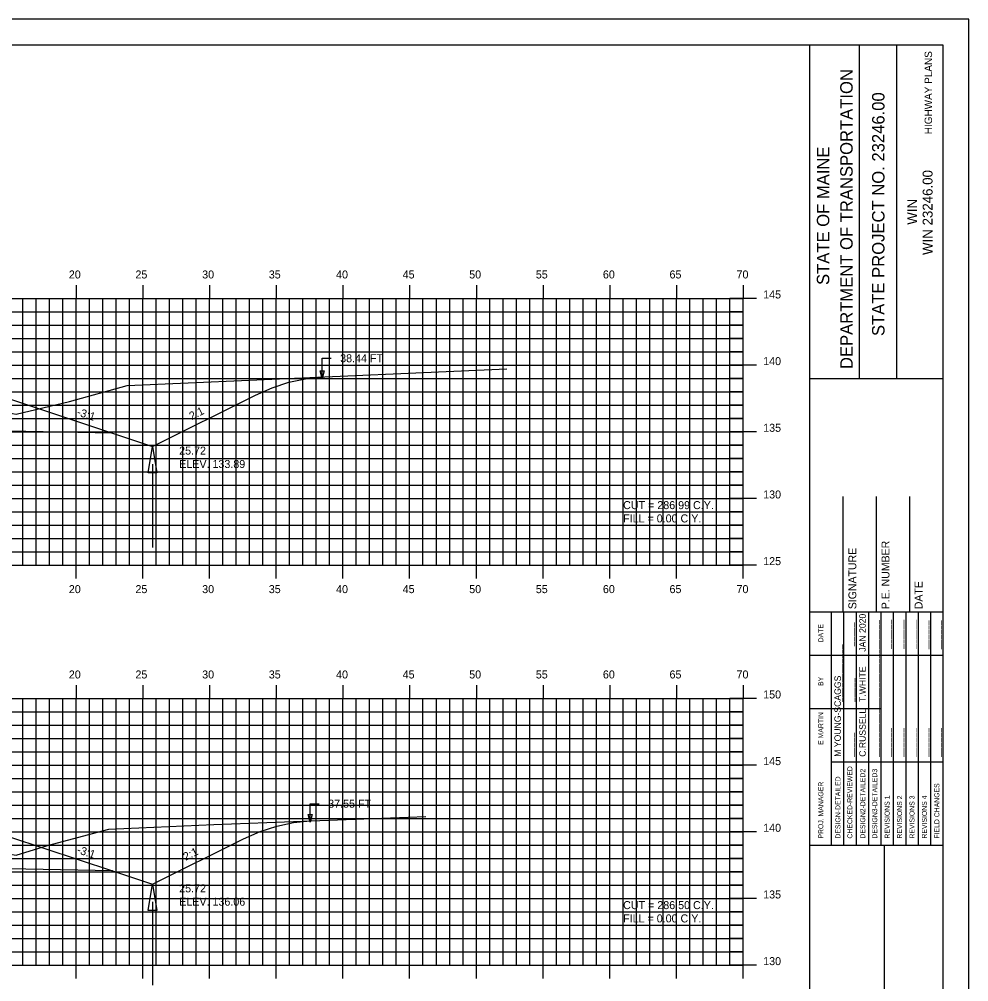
# Model space of a CAD drawing. Extents: x 1145194 to 1145364, y 608981 to 609091.
# Drawn here: x 1145292.9 to 1145364, y 609019.1 to 609091.3 of the extents above; entities that cross this region are included whole.
import ezdxf

# ---------------------------------------------------------------- set-up
doc = ezdxf.new("R2010")
doc.units = 0
for name, color, linetype in [('ANNOTATION', 7, 'Continuous'), ('BORDER', 7, 'Continuous'), ('D_Drainage_Ditch_Line', 7, 'Continuous'), ('D_Roadway_SlopeLines', 7, 'Continuous'), ('D_Roadway_SubGrade', 7, 'Continuous'), ('D_Text_Standard', 7, 'Continuous'), ('H_V ANNOTATION', 7, 'Continuous'), ('HIGHWAY_TITLE', 7, 'Continuous'), ('MAJOR', 7, 'Continuous'), ('MINOR', 7, 'Continuous'), ('PLOT BOUNDARY', 7, 'Continuous'), ('S_Roadway_Centerline', 7, 'Continuous')]:
    doc.layers.add(name, color=color, linetype=linetype)

msp = doc.modelspace()

# ---------------------------------------------------------------- linework, layer by layer
for points in [[(1145240.362, 609063.649), (1145241.612, 609063.504), (1145242.862, 609063.221), (1145244.112, 609062.802), (1145245.362, 609062.245), (1145251.407, 609059.223), (1145254.407, 609060.223), (1145262.131, 609062.797), (1145262.132, 609062.797), (1145266.132, 609062.957), (1145277.132, 609063.177), (1145288.132, 609062.957), (1145292.132, 609062.797), (1145299.855, 609060.223), (1145302.855, 609059.223), (1145310.577, 609063.083), (1145311.827, 609063.637), (1145313.077, 609064.048), (1145314.327, 609064.317), (1145315.577, 609064.443)], [(1145240.436, 609030.623), (1145241.686, 609030.548), (1145242.936, 609030.316), (1145244.186, 609029.927), (1145245.436, 609029.38), (1145251.407, 609026.395), (1145254.407, 609027.395), (1145262.131, 609029.969), (1145262.132, 609029.969), (1145266.132, 609030.129), (1145277.132, 609030.349), (1145288.132, 609030.129), (1145292.132, 609029.969), (1145299.855, 609027.395), (1145302.855, 609026.395), (1145309.682, 609029.808), (1145310.932, 609030.361), (1145312.182, 609030.769), (1145313.432, 609031.033), (1145314.682, 609031.153)]]:
    msp.add_lwpolyline(points)
at = {"layer": 'BORDER'}
for p, q in [((1145352.132, 608984.335), (1145352.132, 609089.335)), ((1145355.861, 609064.332), (1145355.861, 609089.332)), ((1145358.656, 609064.332), (1145358.656, 609089.332)), ((1145352.133, 609064.329), (1145362.132, 609064.329)), ((1145354.632, 609046.838), (1145354.632, 609055.485)), ((1145357.132, 609046.838), (1145357.132, 609055.485)), ((1145359.632, 609046.838), (1145359.632, 609055.485)), ((1145352.132, 609046.838), (1145362.132, 609046.838)), ((1145352.132, 609029.338), (1145362.132, 609029.338)), ((1145357.723, 608994.338), (1145357.723, 609029.338))]:
    msp.add_line(p, q, dxfattribs=at)
msp.add_lwpolyline([(1145202.132, 608984.335), (1145362.132, 608984.335), (1145362.132, 609089.335), (1145202.132, 609089.335)], close=True, dxfattribs=at)
for points in [[(1145353.747, 609043.588), (1145353.747, 609046.838)], [(1145354.68, 609029.341), (1145354.68, 609046.838)], [(1145355.611, 609046.838), (1145355.611, 609029.341)], [(1145356.543, 609029.341), (1145356.543, 609046.838)], [(1145357.475, 609029.341), (1145357.475, 609046.838)], [(1145358.406, 609029.341), (1145358.406, 609046.838)], [(1145359.338, 609029.341), (1145359.338, 609046.838)], [(1145360.27, 609029.341), (1145360.27, 609046.838)], [(1145361.201, 609029.341), (1145361.201, 609046.838)], [(1145353.748, 609029.341), (1145353.748, 609046.132)], [(1145352.132, 609043.588), (1145362.132, 609043.588)], [(1145352.132, 609039.588), (1145353.748, 609039.588)], [(1145353.747, 609039.588), (1145357.474, 609039.588)], [(1145353.747, 609035.588), (1145362.132, 609035.588)]]:
    msp.add_lwpolyline(points, dxfattribs=at)
at = {"layer": 'D_Drainage_Ditch_Line'}
for p, q in [((1145302.856, 609057.91), (1145302.855, 609051.667)), ((1145302.856, 609025.082), (1145302.855, 609018.839))]:
    msp.add_line(p, q, dxfattribs=at)
for points in [[(1145303.184, 609057.254), (1145302.527, 609057.254), (1145302.855, 609059.223)], [(1145303.184, 609024.426), (1145302.527, 609024.426), (1145302.855, 609026.395)]]:
    msp.add_lwpolyline(points, close=True, dxfattribs=at)
at = {"layer": 'D_Roadway_SlopeLines'}
for points in [[(1145302.855, 609059.223), (1145310.577, 609063.083), (1145311.827, 609063.637), (1145313.077, 609064.048), (1145314.327, 609064.317), (1145315.577, 609064.443)], [(1145299.855, 609060.223), (1145302.855, 609059.223)], [(1145302.855, 609026.395), (1145309.682, 609029.808), (1145310.932, 609030.361), (1145312.182, 609030.769), (1145313.432, 609031.033), (1145314.682, 609031.153)], [(1145299.855, 609027.395), (1145302.855, 609026.395)]]:
    msp.add_lwpolyline(points, dxfattribs=at)
at = {"layer": 'D_Roadway_SubGrade'}
for points in [[(1145288.132, 609062.54), (1145288.132, 609062.707), (1145292.132, 609062.547), (1145292.132, 609062.797), (1145292.132, 609062.797), (1145299.855, 609060.223), (1145288.132, 609060.457)], [(1145288.132, 609029.712), (1145288.132, 609029.879), (1145292.132, 609029.719), (1145292.132, 609029.969), (1145292.132, 609029.969), (1145299.855, 609027.395), (1145288.132, 609027.629)]]:
    msp.add_lwpolyline(points, close=True, dxfattribs=at)
at = {"layer": 'D_Text_Standard'}
for points in [[(1145315.577, 609064.333), (1145315.564, 609065.851), (1145316.244, 609065.851)], [(1145314.682, 609031.058), (1145314.669, 609032.443), (1145315.349, 609032.443)]]:
    msp.add_lwpolyline(points, dxfattribs=at)
for points in [[(1145315.577, 609064.333), (1145315.426, 609064.914), (1145315.718, 609064.917)], [(1145314.682, 609031.058), (1145314.531, 609031.639), (1145314.822, 609031.641)]]:
    msp.add_lwpolyline(points, close=True, dxfattribs=at)
at = {"layer": 'MAJOR'}
for p, q in [((1145297.132, 609071.337), (1145297.132, 609070.335)), ((1145302.132, 609071.337), (1145302.132, 609070.335)), ((1145307.132, 609071.337), (1145307.132, 609070.335)), ((1145312.132, 609071.337), (1145312.132, 609070.335)), ((1145317.132, 609071.337), (1145317.132, 609070.335)), ((1145322.132, 609071.337), (1145322.132, 609070.335)), ((1145327.132, 609071.337), (1145327.132, 609070.335)), ((1145332.132, 609071.337), (1145332.132, 609070.335)), ((1145337.132, 609071.337), (1145337.132, 609070.335)), ((1145342.132, 609071.337), (1145342.132, 609070.335)), ((1145347.132, 609071.337), (1145347.132, 609070.335)), ((1145207.132, 609070.335), (1145347.132, 609070.335)), ((1145207.132, 609070.335), (1145347.132, 609070.335)), ((1145297.132, 609050.335), (1145297.132, 609070.335)), ((1145302.132, 609050.335), (1145302.132, 609070.335)), ((1145307.132, 609050.335), (1145307.132, 609070.335)), ((1145312.132, 609050.335), (1145312.132, 609070.335)), ((1145317.132, 609050.335), (1145317.132, 609070.335)), ((1145322.132, 609050.335), (1145322.132, 609070.335)), ((1145327.132, 609050.335), (1145327.132, 609070.335)), ((1145332.132, 609050.335), (1145332.132, 609070.335)), ((1145337.132, 609050.335), (1145337.132, 609070.335)), ((1145342.132, 609050.335), (1145342.132, 609070.335)), ((1145348.134, 609070.335), (1145346.13, 609070.335)), ((1145347.132, 609050.335), (1145347.132, 609070.335)), ((1145347.132, 609050.335), (1145347.132, 609070.335)), ((1145207.132, 609065.335), (1145347.132, 609065.335)), ((1145348.134, 609065.335), (1145346.13, 609065.335)), ((1145207.132, 609060.335), (1145347.132, 609060.335)), ((1145348.134, 609060.335), (1145346.13, 609060.335)), ((1145207.132, 609055.335), (1145347.132, 609055.335)), ((1145348.134, 609055.335), (1145346.13, 609055.335)), ((1145207.132, 609050.335), (1145347.132, 609050.335)), ((1145207.132, 609050.335), (1145347.132, 609050.335)), ((1145297.132, 609049.333), (1145297.132, 609050.335)), ((1145302.132, 609049.333), (1145302.132, 609050.335)), ((1145307.132, 609049.333), (1145307.132, 609050.335)), ((1145312.132, 609049.333), (1145312.132, 609050.335)), ((1145317.132, 609049.333), (1145317.132, 609050.335)), ((1145322.132, 609049.333), (1145322.132, 609050.335)), ((1145327.132, 609049.333), (1145327.132, 609050.335)), ((1145332.132, 609049.333), (1145332.132, 609050.335)), ((1145337.132, 609049.333), (1145337.132, 609050.335)), ((1145342.132, 609049.333), (1145342.132, 609050.335)), ((1145348.134, 609050.335), (1145346.13, 609050.335)), ((1145347.132, 609049.333), (1145347.132, 609050.335)), ((1145297.132, 609041.337), (1145297.132, 609040.335)), ((1145302.132, 609041.337), (1145302.132, 609040.335)), ((1145307.132, 609041.337), (1145307.132, 609040.335)), ((1145312.132, 609041.337), (1145312.132, 609040.335)), ((1145317.132, 609041.337), (1145317.132, 609040.335)), ((1145322.132, 609041.337), (1145322.132, 609040.335)), ((1145327.132, 609041.337), (1145327.132, 609040.335)), ((1145332.132, 609041.337), (1145332.132, 609040.335)), ((1145337.132, 609041.337), (1145337.132, 609040.335)), ((1145342.132, 609041.337), (1145342.132, 609040.335)), ((1145347.132, 609041.337), (1145347.132, 609040.335)), ((1145207.132, 609040.335), (1145347.132, 609040.335)), ((1145207.132, 609040.335), (1145347.132, 609040.335)), ((1145297.132, 609020.335), (1145297.132, 609040.335)), ((1145302.132, 609020.335), (1145302.132, 609040.335)), ((1145307.132, 609020.335), (1145307.132, 609040.335)), ((1145312.132, 609020.335), (1145312.132, 609040.335)), ((1145317.132, 609020.335), (1145317.132, 609040.335)), ((1145322.132, 609020.335), (1145322.132, 609040.335)), ((1145327.132, 609020.335), (1145327.132, 609040.335)), ((1145332.132, 609020.335), (1145332.132, 609040.335)), ((1145337.132, 609020.335), (1145337.132, 609040.335)), ((1145342.132, 609020.335), (1145342.132, 609040.335)), ((1145348.134, 609040.335), (1145346.13, 609040.335)), ((1145347.132, 609020.335), (1145347.132, 609040.335)), ((1145347.132, 609020.335), (1145347.132, 609040.335)), ((1145207.132, 609035.335), (1145347.132, 609035.335)), ((1145348.134, 609035.335), (1145346.13, 609035.335)), ((1145207.132, 609030.335), (1145347.132, 609030.335)), ((1145348.134, 609030.335), (1145346.13, 609030.335)), ((1145207.132, 609025.335), (1145347.132, 609025.335)), ((1145348.134, 609025.335), (1145346.13, 609025.335)), ((1145207.132, 609020.335), (1145347.132, 609020.335)), ((1145207.132, 609020.335), (1145347.132, 609020.335)), ((1145297.132, 609019.333), (1145297.132, 609020.335)), ((1145302.132, 609019.333), (1145302.132, 609020.335)), ((1145307.132, 609019.333), (1145307.132, 609020.335)), ((1145312.132, 609019.333), (1145312.132, 609020.335)), ((1145317.132, 609019.333), (1145317.132, 609020.335)), ((1145322.132, 609019.333), (1145322.132, 609020.335)), ((1145327.132, 609019.333), (1145327.132, 609020.335)), ((1145332.132, 609019.333), (1145332.132, 609020.335)), ((1145337.132, 609019.333), (1145337.132, 609020.335)), ((1145342.132, 609019.333), (1145342.132, 609020.335)), ((1145348.134, 609020.335), (1145346.13, 609020.335)), ((1145347.132, 609019.333), (1145347.132, 609020.335))]:
    msp.add_line(p, q, dxfattribs=at)
at = {"layer": 'MINOR'}
for p, q in [((1145293.132, 609050.335), (1145293.132, 609070.335)), ((1145294.132, 609050.335), (1145294.132, 609070.335)), ((1145295.132, 609050.335), (1145295.132, 609070.335)), ((1145296.132, 609050.335), (1145296.132, 609070.335)), ((1145298.132, 609050.335), (1145298.132, 609070.335)), ((1145299.132, 609050.335), (1145299.132, 609070.335)), ((1145300.132, 609050.335), (1145300.132, 609070.335)), ((1145301.132, 609050.335), (1145301.132, 609070.335)), ((1145303.132, 609050.335), (1145303.132, 609070.335)), ((1145304.132, 609050.335), (1145304.132, 609070.335)), ((1145305.132, 609050.335), (1145305.132, 609070.335)), ((1145306.132, 609050.335), (1145306.132, 609070.335)), ((1145308.132, 609050.335), (1145308.132, 609070.335)), ((1145309.132, 609050.335), (1145309.132, 609070.335)), ((1145310.132, 609050.335), (1145310.132, 609070.335)), ((1145311.132, 609050.335), (1145311.132, 609070.335)), ((1145313.132, 609050.335), (1145313.132, 609070.335)), ((1145314.132, 609050.335), (1145314.132, 609070.335)), ((1145315.132, 609050.335), (1145315.132, 609070.335)), ((1145316.132, 609050.335), (1145316.132, 609070.335)), ((1145318.132, 609050.335), (1145318.132, 609070.335)), ((1145319.132, 609050.335), (1145319.132, 609070.335)), ((1145320.132, 609050.335), (1145320.132, 609070.335)), ((1145321.132, 609050.335), (1145321.132, 609070.335)), ((1145323.132, 609050.335), (1145323.132, 609070.335)), ((1145324.132, 609050.335), (1145324.132, 609070.335)), ((1145325.132, 609050.335), (1145325.132, 609070.335)), ((1145326.132, 609050.335), (1145326.132, 609070.335)), ((1145328.132, 609050.335), (1145328.132, 609070.335)), ((1145329.132, 609050.335), (1145329.132, 609070.335)), ((1145330.132, 609050.335), (1145330.132, 609070.335)), ((1145331.132, 609050.335), (1145331.132, 609070.335)), ((1145333.132, 609050.335), (1145333.132, 609070.335)), ((1145334.132, 609050.335), (1145334.132, 609070.335)), ((1145335.132, 609050.335), (1145335.132, 609070.335)), ((1145336.132, 609050.335), (1145336.132, 609070.335)), ((1145338.132, 609050.335), (1145338.132, 609070.335)), ((1145339.132, 609050.335), (1145339.132, 609070.335)), ((1145340.132, 609050.335), (1145340.132, 609070.335)), ((1145341.132, 609050.335), (1145341.132, 609070.335)), ((1145343.132, 609050.335), (1145343.132, 609070.335)), ((1145344.132, 609050.335), (1145344.132, 609070.335)), ((1145345.132, 609050.335), (1145345.132, 609070.335)), ((1145346.132, 609050.335), (1145346.132, 609070.335)), ((1145207.132, 609069.335), (1145347.132, 609069.335)), ((1145347.132, 609069.335), (1145346.13, 609069.335)), ((1145207.132, 609068.335), (1145347.132, 609068.335)), ((1145347.132, 609068.335), (1145346.13, 609068.335)), ((1145207.132, 609067.335), (1145347.132, 609067.335)), ((1145347.132, 609067.335), (1145346.13, 609067.335)), ((1145207.132, 609066.335), (1145347.132, 609066.335)), ((1145347.132, 609066.335), (1145346.13, 609066.335)), ((1145207.132, 609064.335), (1145347.132, 609064.335)), ((1145347.132, 609064.335), (1145346.13, 609064.335)), ((1145207.132, 609063.335), (1145347.132, 609063.335)), ((1145347.132, 609063.335), (1145346.13, 609063.335)), ((1145207.132, 609062.335), (1145347.132, 609062.335)), ((1145347.132, 609062.335), (1145346.13, 609062.335)), ((1145207.132, 609061.335), (1145347.132, 609061.335)), ((1145347.132, 609061.335), (1145346.13, 609061.335)), ((1145207.132, 609059.335), (1145347.132, 609059.335)), ((1145347.132, 609059.335), (1145346.13, 609059.335)), ((1145207.132, 609058.335), (1145347.132, 609058.335)), ((1145347.132, 609058.335), (1145346.13, 609058.335)), ((1145207.132, 609057.335), (1145347.132, 609057.335)), ((1145347.132, 609057.335), (1145346.13, 609057.335)), ((1145207.132, 609056.335), (1145347.132, 609056.335)), ((1145347.132, 609056.335), (1145346.13, 609056.335)), ((1145207.132, 609054.335), (1145347.132, 609054.335)), ((1145347.132, 609054.335), (1145346.13, 609054.335)), ((1145207.132, 609053.335), (1145347.132, 609053.335)), ((1145347.132, 609053.335), (1145346.13, 609053.335)), ((1145207.132, 609052.335), (1145347.132, 609052.335)), ((1145347.132, 609052.335), (1145346.13, 609052.335)), ((1145207.132, 609051.335), (1145347.132, 609051.335)), ((1145347.132, 609051.335), (1145346.13, 609051.335)), ((1145293.132, 609020.335), (1145293.132, 609040.335)), ((1145294.132, 609020.335), (1145294.132, 609040.335)), ((1145295.132, 609020.335), (1145295.132, 609040.335)), ((1145296.132, 609020.335), (1145296.132, 609040.335)), ((1145298.132, 609020.335), (1145298.132, 609040.335)), ((1145299.132, 609020.335), (1145299.132, 609040.335)), ((1145300.132, 609020.335), (1145300.132, 609040.335)), ((1145301.132, 609020.335), (1145301.132, 609040.335)), ((1145303.132, 609020.335), (1145303.132, 609040.335)), ((1145304.132, 609020.335), (1145304.132, 609040.335)), ((1145305.132, 609020.335), (1145305.132, 609040.335)), ((1145306.132, 609020.335), (1145306.132, 609040.335)), ((1145308.132, 609020.335), (1145308.132, 609040.335)), ((1145309.132, 609020.335), (1145309.132, 609040.335)), ((1145310.132, 609020.335), (1145310.132, 609040.335)), ((1145311.132, 609020.335), (1145311.132, 609040.335)), ((1145313.132, 609020.335), (1145313.132, 609040.335)), ((1145314.132, 609020.335), (1145314.132, 609040.335)), ((1145315.132, 609020.335), (1145315.132, 609040.335)), ((1145316.132, 609020.335), (1145316.132, 609040.335)), ((1145318.132, 609020.335), (1145318.132, 609040.335)), ((1145319.132, 609020.335), (1145319.132, 609040.335)), ((1145320.132, 609020.335), (1145320.132, 609040.335)), ((1145321.132, 609020.335), (1145321.132, 609040.335)), ((1145323.132, 609020.335), (1145323.132, 609040.335)), ((1145324.132, 609020.335), (1145324.132, 609040.335)), ((1145325.132, 609020.335), (1145325.132, 609040.335)), ((1145326.132, 609020.335), (1145326.132, 609040.335)), ((1145328.132, 609020.335), (1145328.132, 609040.335)), ((1145329.132, 609020.335), (1145329.132, 609040.335)), ((1145330.132, 609020.335), (1145330.132, 609040.335)), ((1145331.132, 609020.335), (1145331.132, 609040.335)), ((1145333.132, 609020.335), (1145333.132, 609040.335)), ((1145334.132, 609020.335), (1145334.132, 609040.335)), ((1145335.132, 609020.335), (1145335.132, 609040.335)), ((1145336.132, 609020.335), (1145336.132, 609040.335)), ((1145338.132, 609020.335), (1145338.132, 609040.335)), ((1145339.132, 609020.335), (1145339.132, 609040.335)), ((1145340.132, 609020.335), (1145340.132, 609040.335)), ((1145341.132, 609020.335), (1145341.132, 609040.335)), ((1145343.132, 609020.335), (1145343.132, 609040.335)), ((1145344.132, 609020.335), (1145344.132, 609040.335)), ((1145345.132, 609020.335), (1145345.132, 609040.335)), ((1145346.132, 609020.335), (1145346.132, 609040.335)), ((1145207.132, 609039.335), (1145347.132, 609039.335)), ((1145347.132, 609039.335), (1145346.13, 609039.335)), ((1145207.132, 609038.335), (1145347.132, 609038.335)), ((1145347.132, 609038.335), (1145346.13, 609038.335)), ((1145207.132, 609037.335), (1145347.132, 609037.335)), ((1145347.132, 609037.335), (1145346.13, 609037.335)), ((1145207.132, 609036.335), (1145347.132, 609036.335)), ((1145347.132, 609036.335), (1145346.13, 609036.335)), ((1145207.132, 609034.335), (1145347.132, 609034.335)), ((1145347.132, 609034.335), (1145346.13, 609034.335)), ((1145207.132, 609033.335), (1145347.132, 609033.335)), ((1145347.132, 609033.335), (1145346.13, 609033.335)), ((1145207.132, 609032.335), (1145347.132, 609032.335)), ((1145347.132, 609032.335), (1145346.13, 609032.335)), ((1145207.132, 609031.335), (1145347.132, 609031.335)), ((1145347.132, 609031.335), (1145346.13, 609031.335)), ((1145207.132, 609029.335), (1145347.132, 609029.335)), ((1145347.132, 609029.335), (1145346.13, 609029.335)), ((1145207.132, 609028.335), (1145347.132, 609028.335)), ((1145347.132, 609028.335), (1145346.13, 609028.335)), ((1145207.132, 609027.335), (1145347.132, 609027.335)), ((1145347.132, 609027.335), (1145346.13, 609027.335)), ((1145207.132, 609026.335), (1145347.132, 609026.335)), ((1145347.132, 609026.335), (1145346.13, 609026.335)), ((1145207.132, 609024.335), (1145347.132, 609024.335)), ((1145347.132, 609024.335), (1145346.13, 609024.335)), ((1145207.132, 609023.335), (1145347.132, 609023.335)), ((1145347.132, 609023.335), (1145346.13, 609023.335)), ((1145207.132, 609022.335), (1145347.132, 609022.335)), ((1145347.132, 609022.335), (1145346.13, 609022.335)), ((1145207.132, 609021.335), (1145347.132, 609021.335)), ((1145347.132, 609021.335), (1145346.13, 609021.335))]:
    msp.add_line(p, q, dxfattribs=at)
at = {"layer": 'PLOT BOUNDARY'}
msp.add_lwpolyline([(1145194.039, 608981.276), (1145364.039, 608981.276), (1145364.039, 609091.276), (1145194.039, 609091.276)], close=True, dxfattribs=at)
at = {"layer": 'S_Roadway_Centerline'}
for points in [[(1145221.402, 609064.735), (1145225.329, 609064.575), (1145246.561, 609063.268), (1145248.193, 609062.854), (1145257.196, 609061.684), (1145260.651, 609062.618), (1145261.032, 609062.705), (1145261.259, 609062.722), (1145262.732, 609062.678), (1145271.744, 609062.884), (1145274.056, 609062.93), (1145282.857, 609062.744), (1145285.086, 609062.712), (1145286.013, 609062.635), (1145288.576, 609062.35), (1145292.097, 609061.764), (1145292.643, 609061.658), (1145296.634, 609062.619), (1145300.948, 609063.802), (1145310.099, 609064.202), (1145329.411, 609065.052)], [(1145224.528, 609030.772), (1145234.304, 609030.604), (1145249.208, 609030.65), (1145252.864, 609029.757), (1145257.166, 609028.889), (1145258.819, 609029.378), (1145260.888, 609029.886), (1145261.776, 609029.943), (1145262.584, 609029.963), (1145270.874, 609030.127), (1145273.9, 609030.196), (1145281.879, 609029.922), (1145284.812, 609029.858), (1145287.669, 609029.57), (1145288.499, 609029.477), (1145291.49, 609028.782), (1145292.645, 609028.588), (1145294.997, 609029.318), (1145299.578, 609030.541), (1145307.466, 609030.879), (1145323.345, 609031.482)]]:
    msp.add_lwpolyline(points, dxfattribs=at)

# ---------------------------------------------------------------- texts
at = {"layer": 'ANNOTATION'}
for s, rotation, p in [('-3:1', 341.56521, (1145297.143, 609061.581)), ('2:1', 26.56505, (1145305.789, 609061.207)), ('-3:1', 341.56521, (1145297.143, 609028.753)), ('2:1', 26.56505, (1145305.341, 609028.156))]:
    msp.add_text(s, height=0.6, rotation=rotation, dxfattribs=at).set_placement(p)
at = {"layer": 'BORDER'}
for s, height, p in [('DEPARTMENT OF TRANSPORTATION', 0.93176, (1145355.339, 609065.041)), ('STATE PROJECT NO. 23246.00', 0.93176, (1145357.724, 609067.517)), ('STATE OF MAINE', 0.93176, (1145353.587, 609071.347)), ('WIN 23246.00', 0.74527, (1145361.328, 609073.596)), ('WIN', 0.7453, (1145360.169, 609075.865)), ('SIGNATURE', 0.5906, (1145355.613, 609047.03)), ('P.E. NUMBER', 0.59055, (1145358.093, 609047.03)), ('DATE', 0.5906, (1145360.573, 609047.03)), ('JAN 2020', 0.4845, (1145356.318, 609043.843)), ('DATE', 0.3714, (1145353.136, 609044.544)), ('_____', 0.4845, (1145355.35, 609044.243)), ('______', 0.4845, (1145357.213, 609044.063)), ('______', 0.4845, (1145358.145, 609044.065)), ('______', 0.4845, (1145359.076, 609044.067)), ('______', 0.4845, (1145360.008, 609044.067)), ('______', 0.4845, (1145360.94, 609044.036)), ('______', 0.4845, (1145361.871, 609044.036)), ('____________', 0.48455, (1145354.455, 609040.073)), ('____________', 0.48455, (1145357.213, 609040.073)), ('T.WHITE', 0.4845, (1145356.318, 609040.073)), ('BY', 0.3714, (1145353.136, 609041.273)), ('M YOUNG-SCAGGS', 0.48455, (1145354.455, 609035.961)), ('_____', 0.4845, (1145355.387, 609040.073)), ('____________', 0.48455, (1145357.213, 609035.961)), ('C.RUSSELL', 0.4845, (1145356.318, 609035.961)), ('E MARTIN', 0.3727, (1145353.136, 609036.855)), ('_____', 0.4845, (1145355.35, 609035.961)), ('______', 0.4845, (1145358.145, 609035.961)), ('______', 0.4845, (1145359.076, 609035.961)), ('______', 0.4845, (1145360.008, 609035.961)), ('______', 0.4845, (1145360.94, 609035.961)), ('______', 0.4845, (1145361.871, 609035.961)), ('CHECKED-REVIEWED', 0.37275, (1145355.313, 609029.826)), ('DESIGN2-DETAILED2', 0.37275, (1145356.282, 609029.826)), ('DESIGN3-DETAILED3', 0.37275, (1145357.177, 609029.826)), ('DESIGN-DETAILED', 0.37275, (1145354.419, 609029.826)), ('PROJ. MANAGER', 0.37275, (1145353.136, 609029.826)), ('FIELD CHANGES', 0.37275, (1145361.835, 609029.826)), ('REVISIONS 1', 0.37275, (1145358.108, 609029.826)), ('REVISIONS 2', 0.37275, (1145359.04, 609029.826)), ('REVISIONS 3', 0.37275, (1145359.972, 609029.826)), ('REVISIONS 4', 0.37275, (1145360.903, 609029.826))]:
    msp.add_text(s, height=height, rotation=90, dxfattribs=at).set_placement(p)
at = {"layer": 'D_Text_Standard'}
for s, p in [('38.44 FT', (1145316.924, 609065.551)), ('25.72', (1145304.856, 609058.623)), ('ELEV. 133.89', (1145304.856, 609057.621)), ('CUT = 286.99 C.Y.', (1145338.132, 609054.535)), ('FILL = 0.00 C.Y.', (1145338.132, 609053.539)), ('37.55 FT', (1145316.029, 609032.143)), ('25.72', (1145304.856, 609025.795)), ('ELEV. 136.06', (1145304.856, 609024.793)), ('CUT = 286.50 C.Y.', (1145338.132, 609024.535)), ('FILL = 0.00 C.Y.', (1145338.132, 609023.539))]:
    msp.add_text(s, height=0.6, dxfattribs=at).set_placement(p)
at = {"layer": 'H_V ANNOTATION'}
for s, p in [('20', (1145296.586, 609071.835)), ('25', (1145301.578, 609071.835)), ('30', (1145306.581, 609071.835)), ('35', (1145311.573, 609071.835)), ('40', (1145316.618, 609071.835)), ('45', (1145321.61, 609071.835)), ('50', (1145326.597, 609071.835)), ('55', (1145331.589, 609071.835)), ('60', (1145336.618, 609071.835)), ('65', (1145341.61, 609071.835)), ('70', (1145346.634, 609071.835)), ('145', (1145348.632, 609070.335)), ('140', (1145348.632, 609065.335)), ('135', (1145348.632, 609060.335)), ('130', (1145348.632, 609055.335)), ('125', (1145348.632, 609050.335)), ('20', (1145296.586, 609048.235)), ('25', (1145301.578, 609048.235)), ('30', (1145306.581, 609048.235)), ('35', (1145311.573, 609048.235)), ('40', (1145316.618, 609048.235)), ('45', (1145321.61, 609048.235)), ('50', (1145326.597, 609048.235)), ('55', (1145331.589, 609048.235)), ('60', (1145336.618, 609048.235)), ('65', (1145341.61, 609048.235)), ('70', (1145346.634, 609048.235)), ('20', (1145296.586, 609041.835)), ('25', (1145301.578, 609041.835)), ('30', (1145306.581, 609041.835)), ('35', (1145311.573, 609041.835)), ('40', (1145316.618, 609041.835)), ('45', (1145321.61, 609041.835)), ('50', (1145326.597, 609041.835)), ('55', (1145331.589, 609041.835)), ('60', (1145336.618, 609041.835)), ('65', (1145341.61, 609041.835)), ('70', (1145346.634, 609041.835)), ('150', (1145348.632, 609040.335)), ('145', (1145348.632, 609035.335)), ('140', (1145348.632, 609030.335)), ('135', (1145348.632, 609025.335)), ('130', (1145348.632, 609020.335))]:
    msp.add_text(s, height=0.6, dxfattribs=at).set_placement(p)
at = {"layer": 'HIGHWAY_TITLE'}
msp.add_text('HIGHWAY PLANS', height=0.55901, rotation=90, dxfattribs=at).set_placement((1145361.29, 609082.65))

doc.saveas('drawing.dxf')
